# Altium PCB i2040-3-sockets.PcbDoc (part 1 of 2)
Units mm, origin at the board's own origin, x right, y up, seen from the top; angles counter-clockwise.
Board outline 210 x 90 mm, 2 copper layers (Top Layer, Bottom Layer), stack 1.575 mm thick; 146 components, 88 nets, 453 pads, 125 vias.
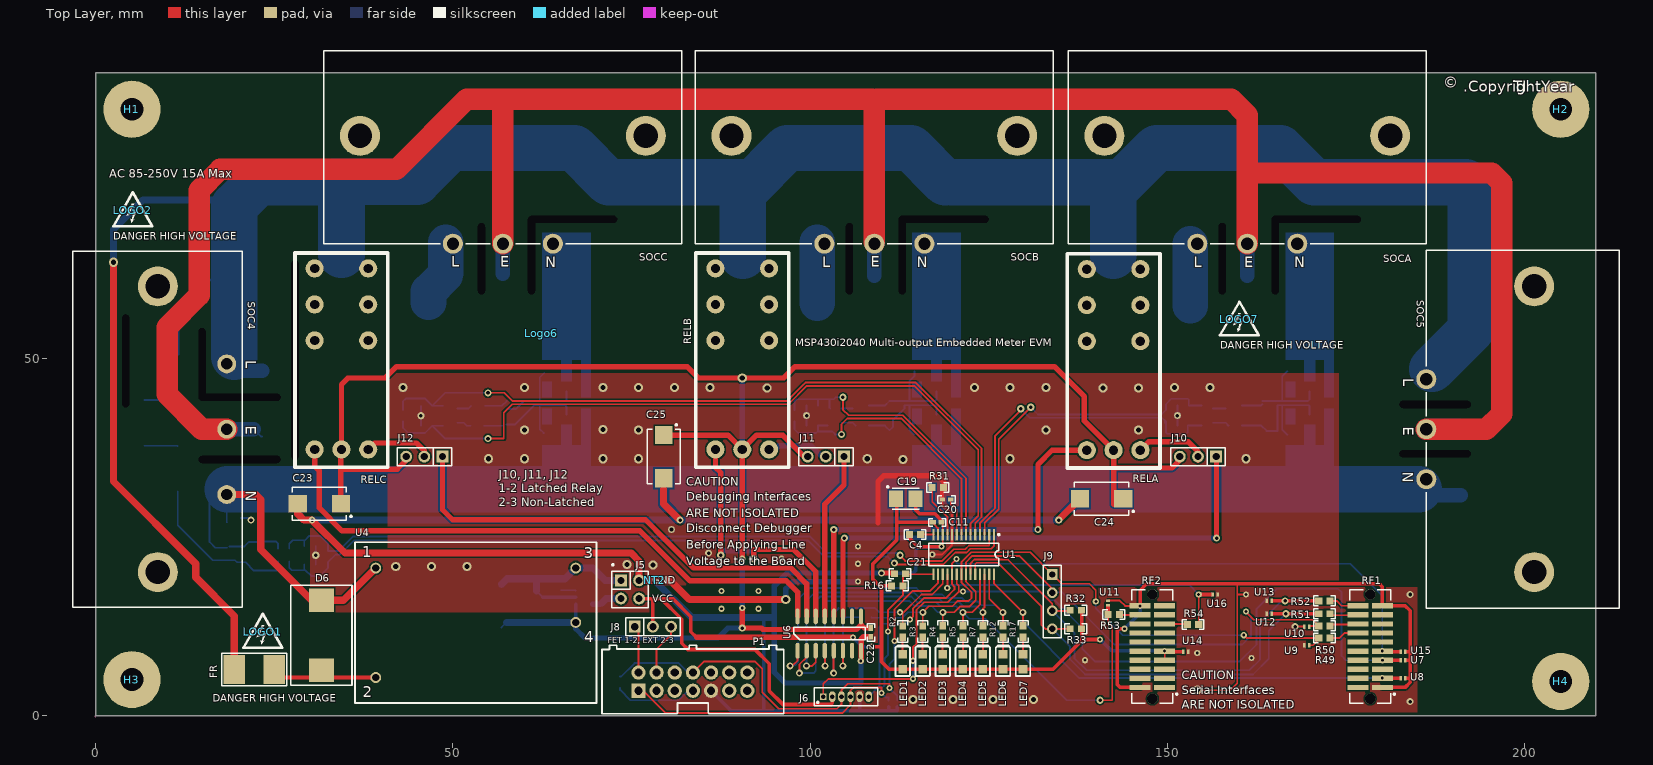
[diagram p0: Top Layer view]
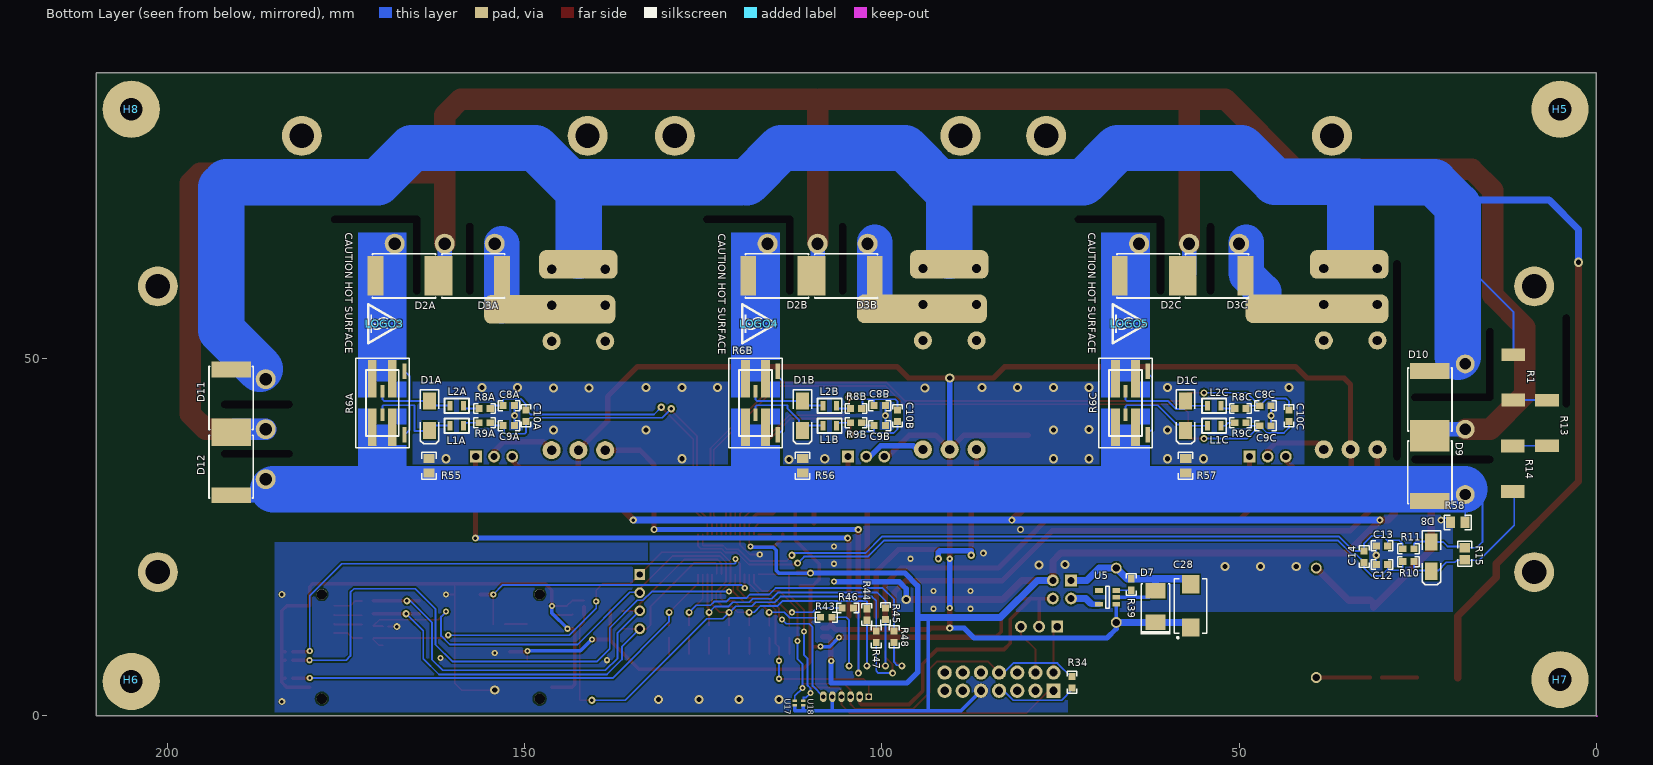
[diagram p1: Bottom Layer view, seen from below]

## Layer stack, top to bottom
Top Layer: signal copper 0.0356
Dielectric: core 1.5037, FR-4, Dk 4.8
Bottom Layer: signal copper 0.0356

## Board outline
0,0 0,90 210,90 210,0

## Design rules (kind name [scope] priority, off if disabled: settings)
AcuteAngle [All] p1: minimum=4.50000000000000E+0001 checktracksonly=FALSE
AssemblyTestPointUsage [All] p1: valid=2
Clearance Clearance_2 [InNet('DGND')] p1: gap=0.254
Clearance Clearance_1 [InNet('AGND')] p2: gap=0.254
Clearance Clearance_BoardEdge_MountingHoles [OnCopper and InComponentClass('Mounting Holes') vs IsKeepOut] p3: gap=1.016
Clearance Clearance_BoardEdge_Poly [OnCopper and InPoly vs IsKeepOut] p4: gap=0.635
Clearance Clearance_BoardEdge [OnCopper and Not InComponentClass('Logo') and not InComponentClass('FiducialMark') and not InRegion(1000,500,4000,800) and Not IsKeepout vs IsKeepOut] p5: gap=1.905
Clearance Clearance_Poly [InPolygon] p6: gap=0.635
Clearance [All] p7: gap=0.203
ComponentClearance ComponentClearance_Shunt [InComponentClass('Header') vs InComponentClass('Shunt')] p1: gap=0 collisioncheckmode=3 verticalgap=0 showdistances=TRUE
ComponentClearance ComponentClearance_Logo [InComponentClass('Logo')] p2: gap=0.5 collisioncheckmode=3 verticalgap=0.254 showdistances=TRUE
ComponentClearance ComponentClearance_ScrewToNut [(HasFootprint('NY PMS 440 0025 PH')) vs (HasFootprint('Keystone_1902C'))] p3: gap=0.127 collisioncheckmode=3 verticalgap=0.254 showdistances=TRUE
ComponentClearance ComponentClearance_MountingHoles [InComponentClass('Mounting Holes')] p4: gap=6.35 collisioncheckmode=3 verticalgap=2540 showdistances=TRUE
ComponentClearance ComponentClearance_SmallPassives [HasFootprint('0201*') or HasFootprint('0402*') or HasFootprint('0508') or HasFootprint('0603*') or HasFootprint('0612') or HasFootprint('0805*') or HasFootprint('0815*') or HasFootprint('0830*') or HasFootprint('1206*') or HasFootprint('1210*') or HasFootprint('1808*') or HasFootprint('1812*') or HasFootprint('1825*') or HasFootprint('2010*') or HasFootprint('2220*') or HasFootprint('2225*') or HasFootprint('2512*') or HasFootprint('2728*') or HasFootprint('3518*') vs HasFootprint('0201*') or HasFootprint('0402*') or HasFootprint('0508') or HasFootprint('0603*') or HasFootprint('0612') or HasFootprint('0805*') or HasFootprint('0815*') or HasFootprint('0830*') or HasFootprint('1206*') or HasFootprint('1210*') or HasFootprint('1808*') or HasFootprint('1812*') or HasFootprint('1825*') or HasFootprint('2010*') or HasFootprint('2220*') or HasFootprint('2225*') or HasFootprint('2512*') or HasFootprint('2728*') or HasFootprint('3518*')] p5: gap=0.508 collisioncheckmode=3 verticalgap=0.254 showdistances=TRUE
ComponentClearance ComponentClearance_THtoSMT [IsThruComponent vs IsSMTComponent] p6: gap=1 collisioncheckmode=3 verticalgap=0.762 showdistances=TRUE
ComponentClearance ComponentClearance_THtoTH [IsThruComponent vs IsThruComponent] p7: gap=1 collisioncheckmode=3 verticalgap=0.762 showdistances=TRUE
ComponentClearance [All] p8: gap=0.5 collisioncheckmode=3 verticalgap=0.254 showdistances=TRUE
DiffPairsRouting [All] p1: maxlimit=2.54 minlimit=0.254 mostfreqgap=0.254 maxuncoupledlength=25.4
FabricationTestPointUsage TestPointUsage [All] p1: valid=2 allowmultiple=FALSE
FabricationTestpoint Testpoint [All] p1: side=3 testpointundercomponent=TRUE minsize=1.016 maxsize=2.54 preferedsize=1.524 minholesize=0 maxholesize=1.016 preferedholesize=0.813 testpointgrid=0.025 allowsidetop=TRUE allowsidebottom=TRUE usegrid=TRUE gridtolerance=0
FanoutControl Fanout_LCC [IsLCC] p1: bgadir=Out bgaviamode=Centered fanoutstyle=Auto fanoutdirection=Alternating viagrid=0.025 // Fanout_LCC (Default Rule)
FanoutControl Fanout_BGA [IsBGA] p2: bgadir=Out bgaviamode=Centered fanoutstyle=Auto fanoutdirection=Alternating viagrid=0.025 // Fanout_BGA (Default Rule)
FanoutControl Fanout_Default [All] p4: bgadir=Out bgaviamode=Centered fanoutstyle=Auto fanoutdirection=Alternating viagrid=0.025 // Fanout_Default (Default Rule)
FanoutControl Fanout_Small [(CompPinCount < 5)] p5: bgadir=Out bgaviamode=Centered fanoutstyle=Auto fanoutdirection=OutThenIn viagrid=0.025 // Fanout_Small (Default Rule)
HoleSize [All] p1: absolutevalues=TRUE maxlimit=6.375 minlimit=0.203 maxpercent=80.000 minpercent=20.000
MinimumAnnularRing MinimumAnnularRing_ThermalPadVias [IsVia and InAnyComponent] p1: minimumring=0.15
MinimumAnnularRing [All] p2: minimumring=0.229
MinimumSolderMaskSliver MinimumSolderMaskSliver_Logo [InComponentClass('Logo') vs InComponentClass('Logo')] p1: minsoldermaskwidth=0.018
MinimumSolderMaskSliver [All] p2: minsoldermaskwidth=0.1
PlaneClearance [All] p1: clearance=0.254
PlaneConnect [All] p1: planeconnectstyle=Direct reliefexpansion=0.254 reliefentries=4 reliefconductorwidth=0.254 reliefairgap=0.254
PolygonConnect PolygonConnect_1 [InNet('DGND') vs IsNamedPolygon('Top Layer-DGND')] p1: connectstyle=Direct reliefconductorwidth=0.254 reliefentries=4 polygonreliefangle="90 Angle" airgapwidth=0.254
PolygonConnect [InNet('AGND')] p2: connectstyle=Direct reliefconductorwidth=0.254 reliefentries=4 polygonreliefangle="90 Angle" airgapwidth=0.254
RoomDefinition Protection [InComponentClass('Protection')] p1: confinementstyle=ConfineOut formatcopy=TRUE lockcomponents=FALSE outline 150,140 150,170 80,170 80,140.4 80.4,140
RoomDefinition i2040-3-sockets [InComponentClass('i2040-3-sockets')] p2: confinementstyle=ConfineOut formatcopy=TRUE lockcomponents=FALSE outline 176,133 236,133 236,162 176.2,162 176,162.2
RoomDefinition Hardware [InComponentClass('Hardware')] p3: confinementstyle=ConfineOut formatcopy=TRUE lockcomponents=FALSE outline 233.426,70.104 244.094,70.104 244.094,116.078 233.426,116.078
RoutingVias ThermalPadVias [IsVia and InAnyComponent] p1: holewidth=0.2 width=0.5 viastyle="Through Hole" minholewidth=0.2 minwidth=0.5 maxholewidth=0.33 maxwidth=0.6
RoutingVias [All] p2: holewidth=0.406 width=0.864 viastyle="Through Hole" minholewidth=0.2 minwidth=0.66 maxholewidth=1.016 maxwidth=1.651
SMDToCorner [All] p1: distance=30000
SilkToSilkClearance [All] p1: silktosilkclearance=0.127
SilkscreenOverComponentPads [All] p1: minsilkscreentomaskgap=0.127
SolderMaskExpansion [All] p1: expansion=0.05
Width [All] p1: maxlimit=7 minlimit=0.152 preferedwidth=0.254 checkconnectedcopper=TRUE
13 further rules are at their usual default settings.

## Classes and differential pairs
component class "Mounting Holes": H1 H2 H3 H4
component class Logo: Logo6
component class Hardware: H1 H2 H3 H4 H5 H6 H7 H8 LOGO1 LOGO2 LOGO3 LOGO4 LOGO5 Logo6 LOGO7 Logo?
component class Header: J5 J8 J10 J11 J12
component class i2040-3-sockets: 0.8 C4 C8A C8B C8C C9A C9B C9C C10A C10B C10C C11 C12 C13 C14 C19 C20 C21 C22 C23 C24 C25 C28 D1A D1B D1C D6 D7 D8 FR J5 J6 J8 J9 J10 J11 J12 L1A L1B L1C L2A L2B L2C LED1 LED2 LED3 LED4 LED5 LED6 LED7 NT2 P1 R1 R2 R3 R4 R5 R6A R6B R6C R7 R8A R8B R8C R9A R9B R9C R10 R11 R12 R13 R14 R15 R16 R17 R31 R32 R33 R34 R39 R43 R44 R45 R46 R47 R48 R49 R50 R51 R52 R53 R54 R55 R56 R57 R58 RELA RELB RELC RF1 RF2 SOC4 SOC5 SOCA SOCB SOCC U1 U4 U5 U6
component class Protection: D2A D2B D2C D3A D3B D3C D9 D10 D11 D12 U7 U8 U9 U10 U11 U12 U13 U14 U15 U16 U17 U18

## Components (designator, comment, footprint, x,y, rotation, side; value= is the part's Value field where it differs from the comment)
C4 "470nF" 0603 114.7,25.4 r180 top
C8A "06035A470JAT2A" 0603 152.218,43.434 r0 bottom
C8B "06035A470JAT2A" 0603 100.318,43.434 r0 bottom
C8C "06035A470JAT2A" 0603 46.318,43.425 r0 bottom
C9A "06035A470JAT2A" 0603 152.218,40.634 r180 bottom
C9B "06035A470JAT2A" 0603 100.318,40.634 r180 bottom
C9C "06035A470JAT2A" 0603 46.318,40.625 r180 bottom
C10A "GRM188R71C153KA01D" 0603 149.818,42.034 r90 bottom
C10B "GRM188R71C153KA01D" 0603 97.818,42.034 r90 bottom
C10C "GRM188R71C153KA01D" 0603 43.018,42.025 r90 bottom
C11 "0.1uF" 0402 117.8,27.1 r0 top
C12 "06035A470JAT2A" 0603 30,21.2 r0 bottom
C13 "06035A470JAT2A" 0603 30,23.8 r180 bottom
C14 "GRM188R71C153KA01D" 0603 32.5,22.3 r90 bottom
C19 "293D106X0010B2TE3" 3528-21 113.4,30.4 r0 top
C20 "0.1uF" 0402 119.1,30.3 r180 top
C21 "C0603X222K5RACTU" 0603 112.6,19.9 r180 top
C22 "0.1uF" 0402 108.5,11.7 r270 top
C23 "293D227X96R3D2TE3" 7343-31 31.3,29.7 r180 top
C24 "293D227X96R3D2TE3" 7343-31 140.8,30.4 r180 top
C25 "293D227X96R3D2TE3" 7343-31 79.5,36.3 r270 top
C28 "293D227X96R3D2TE3" 7343-31 56.8,15.4 r90 bottom
D1A "SMAJ5.0CA" DSO-C2/X1.8 163.318,42.025 r270 bottom
D1B "SMAJ5.0CA" DSO-C2/X1.8 111.118,42.025 r270 bottom
D1C "SMAJ5.0CA" DSO-C2/X1.8 57.518,42.025 r270 bottom
D2A "V430CH8T" V430CH8T 166.9,61.6 r0 bottom
D2B "V430CH8T" V430CH8T 114.7,61.6 r0 bottom
D2C "V430CH8T" V430CH8T 62.7,61.6 r0 bottom
D3A "V430CH8T" V430CH8T 157.2,61.6 r180 bottom
D3B "V430CH8T" V430CH8T 105,61.6 r180 bottom
D3C "V430CH8T" V430CH8T 53.1,61.6 r180 bottom
D6 "V320SM7" V320SM7 31.6,11.3 r90 top
D7 "SMBJ7.0A-13-F" SMB 61.7,15.3 r90 bottom
D8 "SMAJ5.0CA" DSO-C2/X1.8 23.1,22.3 r270 bottom
D9 "V430CH8T" V430CH8T 23.3,34.1 r270 bottom
D10 "V430CH8T" V430CH8T 23.3,44.3 r90 bottom
D11 "V430CH8T" V430CH8T 191.1,44.5 r90 bottom
D12 "V430CH8T" V430CH8T 191.1,34.9 r90 bottom
FR "6125FA1A" 6125FA 22.2,6.5 r180 top
H1 "NY PMS 440 0025 PH" "NY PMS 440 0025 PH"#1 5.08,84.92 r0 top locked
H2 "NY PMS 440 0025 PH" "NY PMS 440 0025 PH"#1 205.072,84.92 r0 top locked
H3 "NY PMS 440 0025 PH" "NY PMS 440 0025 PH"#1 5.08,5.08 r0 top locked
H4 "NY PMS 440 0025 PH" "NY PMS 440 0025 PH"#2 205.072,5.08 r0 top locked
H5 "1902C" Keystone_1902C#1 5.08,84.92 r180 bottom locked
H6 "1902C" Keystone_1902C#2 205.075,5.08 r180 bottom
H7 "1902C" Keystone_1902C#1 5.08,5.08 r180 bottom locked
H8 "1902C" Keystone_1902C#1 205.072,84.92 r180 bottom locked
J5 "TSW-102-07-G-D" TSW-102-07-G-D 74.8,17.7 r270 top
J6 "Used in BOM report" "6-pin header (1.27mm)" 105,2.7 r0 top
J8 "PBC03SAAN" PBC03SAAN 78,12.5 r0 top
J9 "Header 4" HDR1X4 133.9,19.8 r270 top
J10 "PBC03SAAN" PBC03SAAN 154.3,36.3 r180 top
J11 "PBC03SAAN" PBC03SAAN 102.2,36.3 r180 top
J12 "PBC03SAAN" PBC03SAAN 46,36.3 r180 top
L1A "BLM21BD121SN1D" YW0805 159.518,40.634 r0 bottom
L1B "BLM21BD121SN1D" YW0805 107.318,40.634 r0 bottom
L1C "BLM21BD121SN1D" YW0805 53.5,40.6 r0 bottom
L2A "BLM21BD121SN1D" YW0805 159.518,43.434 r0 bottom
L2B "BLM21BD121SN1D" YW0805 107.318,43.434 r0 bottom
L2C "BLM21BD121SN1D" YW0805 53.5,43.4 r0 bottom
LED1 "Used in BOM report" 0805-LED 112.952,7.606 r90 top
LED2 "Used in BOM report" 0805-LED 115.752,7.606 r90 top
LED3 "Used in BOM report" 0805-LED 118.552,7.617 r90 top
LED4 "Used in BOM report" 0805-LED 121.382,7.617 r90 top
LED5 "Used in BOM report" 0805-LED 124.182,7.617 r90 top
LED6 "Used in BOM report" 0805-LED 127,7.617 r90 top
LED7 "Used in BOM report" 0805-LED 129.8,7.617 r90 top
LOGO1 "DANGER HIGH VOLTAGE" IEC_HighVoltage_Small 23.4,11.8 r0 top
LOGO2 "DANGER HIGH VOLTAGE" IEC_HighVoltage_Small 5.2,70.8 r0 top
LOGO3 "CAUTION HOT SURFACE" IEC_HotSurface_Small 169.562,54.9 r270 bottom
LOGO4 "CAUTION HOT SURFACE" IEC_HotSurface_Small 117.186,54.9 r270 bottom
LOGO5 "CAUTION HOT SURFACE" IEC_HotSurface_Small 65.3,54.9 r270 bottom
Logo6 "Texas Instruments" TI_Stacked_SolderMask_Medium 62.4,53.6 r0 top
LOGO7 "DANGER HIGH VOLTAGE" IEC_HighVoltage_Small 160.1,55.5 r0 top
NT2 "Net-Tie" Net-Tie_10mil 78.23,18.97 r180 top net-tie
P1 "MHDR2X7" 2X7BOXHEADER 83.6,4.8 r0 top
R1 "330k" R2512 11.6,47.4 r270 bottom
R2 "390" 0603 112.97,11.806 r270 top
R3 "390" 0603 115.77,11.806 r270 top
R4 "390" 0603 118.57,11.817 r270 top
R5 "390" 0603 121.4,11.817 r270 top
R6A "Used in BOM report" "CURRENT SENSING PAD" 169.924,43.8 r90 bottom
R6B "Used in BOM report" "CURRENT SENSING PAD" 117.7,43.8 r90 bottom
R6C "Used in BOM report" "CURRENT SENSING PAD" 65.9,43.8 r90 bottom
R7 "390" 0603 124.2,11.817 r270 top
R8A "1.00k" 0603 155.618,43.034 r180 bottom
R8B "1.00k" 0603 103.618,43.034 r180 bottom
R8C "1.00k" 0603 49.818,43.025 r180 bottom
R9A "1.00k" 0603 155.618,41.034 r180 bottom
R9B "1.00k" 0603 103.618,41.034 r180 bottom
R9C "1.00k" 0603 49.818,41.025 r180 bottom
R10 "100" 0603 26.3,21.6 r0 bottom
R11 "1.00k" 0603 26.3,23.4 r0 bottom
R12 "390" 0603 127.018,11.817 r270 top
R13 "330k" R2512 6.9,41 r270 bottom
R14 "330k" R2512 11.7,34.6 r270 bottom
R15 "1.50k" 0805 18.4,22.7 r270 bottom
R16 "4.7k" 0603 112.2,18.2 r0 top
R17 "390" 0603 129.818,11.817 r270 top
R31 "Open" 0603 117.873,31.973 r180 top
R32 "Open" 0603 137.2,14.8 r0 top
R33 "Open" 0603 137.2,12.2 r0 top
R34 "330" 0603 73.4,4.7 r270 bottom
R39 "0" 0603 65.1,18.4 r90 bottom
R43 "0" 0603 107.8,13.8 r180 bottom
R44 "0" 0603 102.1,14.2 r270 bottom
R45 "0" 0603 99.5,14.3 r270 bottom
R46 "0" 0603 104.8,15.1 r180 bottom
R47 "0" 0603 100.8,11.1 r270 bottom
R48 "0" 0603 98.3,11.1 r270 bottom
R49 "0" 0603 172,10.9 r180 top
R50 "0" 0603 172,12.6 r180 top
R51 "0" 0603 172,14.3 r180 top
R52 "0" 0603 172,16.1 r180 top
R53 "0" 0603 142.5,14.2 r180 top
R54 "0" 0603 153.6,12.8 r180 top
R55 "CRCW08050000Z0EA" 0805_HV 163.4,35 r270 bottom
R56 "CRCW08050000Z0EA" 0805_HV 111.1,35 r270 bottom
R57 "CRCW08050000Z0EA" 0805_HV 57.5,35 r270 bottom
R58 "CRCW08050000Z0EA" 0805_HV 19.4,27.1 r180 bottom
RELA "RT314F05" "TE RELAY TYPE A" 142.486,64.7 r90 top
RELB "RT314F05" "TE RELAY TYPE A" 90.508,64.8 r90 top
RELC "RZ031A4D005" "TE RELAY TYPE A" 34.4,64.8 r90 top
RF1 "TFM-110-02-S-D-A-K-TR" Samtec_TFM-110-02-S-D-A-K 178.4,9.7 r90 top
RF2 "TFM-110-02-S-D-A-K-TR" Samtec_TFM-110-02-S-D-A-K 147.92,9.7 r90 top
SOC4 "Plug AC Male" IEC9.14-2H3 0,40.132 r180 top locked
SOC5 "Plug AC Female" IEC7-2H3 210.058,40.132 r0 top locked
SOCA "Plug AC Female" IEC7-2H3 161.2,89.9 r90 top locked
SOCB "Plug AC Female" IEC7-2H3 109,89.9 r90 top locked
SOCC "Plug AC Female" IEC7-2H3 57,89.9 r90 top locked
U1 "MSP430i2040PW" TSSO10x6-G28 121.5,22.6 r180 top
U4 "Used in BOM report" VSK-S1 39.2,20.7 r0 top
U5 "TPS77033DBVT" DBV0005A_N 68.4,16.6 r0 bottom
U6 "ULN2003LVDR" D0016A_N 102.698,11.529 r90 top
U7 "TPD1E10B06DPYT" DPY0002A_N 183,7.8 r0 top
U8 "TPD1E10B06DPYT" DPY0002A_N 183,5.3 r0 top
U9 "TPD1E10B06DPYT" DPY0002A_N 169.5,9.9 r180 top
U10 "TPD1E10B06DPYT" DPY0002A_N 169.5,12.5 r180 top
U11 "TPD1E10B06DPYT" DPY0002A_N 141.7,15.8 r90 top
U12 "TPD1E10B06DPYT" DPY0002A_N 164.3,14.3 r180 top
U13 "TPD1E10B06DPYT" DPY0002A_N 164.3,16.1 r180 top
U14 "TPD1E10B06DPYT" DPY0002A_N 152.6,9 r0 top
U15 "TPD1E10B06DPYT" DPY0002A_N 183,9 r0 top
U16 "TPD1E10B06DPYT" DPY0002A_N 156.7,17 r0 top
U17 "TPD1E10B06DPYT" DPY0002A_N 112.2,1.8 r270 bottom
U18 "TPD1E10B06DPYT" DPY0002A_N 111,1.8 r270 bottom

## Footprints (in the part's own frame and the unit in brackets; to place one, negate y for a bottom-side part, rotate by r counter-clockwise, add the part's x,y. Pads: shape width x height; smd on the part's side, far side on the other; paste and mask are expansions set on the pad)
2X7BOXHEADER [mm]
  rect 2x2 hole 1.15: 1(-7.62,-1.27)
  round 2 hole 1.15: 2(-7.62,1.27) 3(-5.08,-1.27) 4(-5.08,1.27) 5(-2.54,-1.27) 6(-2.54,1.27) 7(0,-1.27) 8(0,1.27) 9(2.54,-1.27) 10(2.54,1.27) 11(5.08,-1.27) 12(5.08,1.27) 13(7.62,-1.27) 14(7.62,1.27)
  silkscreen extent -12.72,-4.5 12.72,5.08
"6-pin header (1.27mm)" [mm] "6 pin header 1.27mm"
  rect 0.9x0.9 hole 0.65 mask+0: 1(-3.15,0)
  oval 0.9x1.5 hole 0.65 mask+0: 2(-1.88,0) 3(-0.61,0) 4(0.66,0) 5(1.93,0) 6(3.2,0)
  silkscreen extent -4.42,-1.27 4.47,1.27
0402 [mm] "0402 from SM-752 data"
  rect 0.8x0.6 smd: 1(-0.6,0) 2(0.6,0)
  silkscreen extent -1.22,-0.52 1.22,0.52, body extent -0.55,-0.3 0.55,0.3, height 0.6
0603 [mm] "0603 from SM-752 data"
  rect 1x0.95 smd: 1(-0.8,0) 2(0.8,0)
  silkscreen extent -1.52,-0.69 1.52,0.69, body extent -0.87,-0.47 0.87,0.47, height 0.85
0805 [mm] "0805 from SM-752 data"
  rect 1.3x1.5 smd: 1(-0.85,0) 2(0.85,0)
  silkscreen extent -1.72,-0.97 1.72,0.97, body extent -1.1,-0.72 1.1,0.72, height 1.1
0805-LED [mm]
  rect 1.2x1.2 smd: 1(-1.055,-0.005) 2(1.045,-0.005)
  silkscreen extent -2.01,-1.02 2.26,1.01
0805_HV [mil] "0805 with 30mil clearance between pads"
  rect 50x63 smd: 1(-40,0) 2(40,0)
  silkscreen extent -74,-40 74,40, body extent -43,-29 43,29, height 43
3528-21 [mm] "Medium Density IPC, based on SM-782 section 8.4"
  rect 1.95x2.25 smd: 1(-1.375,0) 2(1.375,0)
  silkscreen extent -2.66,-1.5 1.9,1.79, body extent -1.85,-1.5 1.85,1.5, height 2.1
6125FA [mm] "Cooper Bussman 6125FA Brick Fuses, recommended land pattern OC-2531 Rev. I 3/07"
  rect 3x4 smd: 1(-2.8,0) 2(2.8,0)
  silkscreen extent -4.58,-2.27 4.57,2.28, body extent -3.17,-1.42 3.17,1.41, height 2.84
7343-31 [mm] "Medium Density based on Kemet T495 dimensions"
  rect 2.55x2.45 smd: 1(-3.025,0) 2(3.025,0)
  silkscreen extent -4.56,-2.3 3.8,2.3, body extent -3.8,-2.3 3.8,2.3, height 3.1
"CURRENT SENSING PAD" [mm] "Current Sensing Pad for 2512"
  rect 5.2x1.2 smd: 1(3.4,-1.4) 1(3.4,1.4) 2(-3.4,-1.4) 2(-3.4,1.4)
  rect 1.7x0.6 smd: 3(1.65,0) 4(-1.65,0)
  rect 2.2x0.6 smd: 5(4.45,-3.1) 6(-4.45,-3.1)
  Top Layer region: 0.8,-2 3,-2 3,-3.4 0.8,-3.4
  Top Layer region: -3,-2 -0.8,-2 -0.8,-3.4 -3,-3.4
  Top Layer region: 3,0.8 6,0.8 6,-0.8 3,-0.8
  Top Layer region: -6,0.8 -3,0.8 -3,-0.8 -6,-0.8
  Top Layer region: -6,3.4 -0.8,3.4 -0.8,2 -6,2
  Top Layer region: 0.8,3.4 6,3.4 6,2 0.8,2
  silkscreen extent -6.25,-3.75 6.25,3.75
D0016A_N [mm] "SOIC, 16-Leads, Body 9.9x3.9mm, Pitch 1.27mm, IPC Medium Density"
  oval 2.2x0.6 smd: 1(-2.4,4.445) 2(-2.4,3.175) 3(-2.4,1.905) 4(-2.4,0.635) 5(-2.4,-0.635) 6(-2.4,-1.905) 7(-2.4,-3.175) 8(-2.4,-4.445) 9(2.4,-4.445) 10(2.4,-3.175) 11(2.4,-1.905) 12(2.4,-0.635) 13(2.4,0.635) 14(2.4,1.905) 15(2.4,3.175) 16(2.4,4.445)
  silkscreen extent -0.9,-5 0.9,5, body extent -3,-4.95 3,4.95, height 1.59
DBV0005A_N [mm] "SOT23, 5-Leads, Body 2.9x1.6mm, Pitch 0.95mm, Lead Span 2.8mm, IPC Medium Density"
  rect 1.1x0.65 smd: 1(-1.2,0.95) 2(-1.2,0) 3(-1.2,-0.95) 4(1.2,-0.95) 5(1.2,0.95)
  silkscreen extent -0.25,-1.55 0.25,1.55, body extent -1.42,-1.46 1.42,1.46, height 1.08
DPY0002A_N [mm] "DFN, 2-Leads, Body 1.0x0.6x0.4mm, IPC Medium Density"
  rect 0.35x0.62 smd: 1(-0.34,0) 2(0.34,0)
  body extent -0.5,-0.3 0.5,0.3, height 0.4
DSO-C2/X1.8 [mm] "DO-214-AC/SMA; 2 C-Bend Leads; Body 5 x 2.7 mm, inc. leads (LxW)"
  rect 2.4x1.8 smd: 1(-2.05,0) 2(2.05,0)
  silkscreen extent -3.65,-1.3 3.95,1.3
HDR1X4 [mm] "Connector; Header; 4 Position"
  rect 1.5x1.5 hole 0.9: 1(0,0)
  round 1.5 hole 0.9: 2(2.54,0) 3(5.08,0) 4(7.62,0)
  silkscreen extent -1.27,-1.27 8.89,1.27
IEC7-2H3 [mm] "Mains Power Outlet, IEC60 320-2-2 F, PC Flange Rear Mount"
  round 2.8 hole 1.7: 1(-23.8,7) 2(-23.8,-7) 3(-23.8,0)
  round 5.6 hole 3.4: MH1(-8.7,20) MH2(-8.7,-20)
  silkscreen extent -23.8,-25.05 3.2,25.05
IEC9.14-2H3 [mm] "Mains Power Inlet, IEC60 320-1 C14, PC Flange Rear Mount"
  round 2.65 hole 1.6: 1(-18.35,-9.14) 2(-18.35,9.14) 3(-18.35,0)
  round 5.6 hole 3.4: MH1(-8.7,20) MH2(-8.7,-20)
  silkscreen extent -20.5,-24.9 3.2,24.9
IEC_HighVoltage_Small [mm]
  silkscreen extent -2.72,-2.24 2.72,2.47
IEC_HotSurface_Small [mm]
  silkscreen extent -2.72,-2.36 2.72,2.35
Keystone_1902C#1 [mm] "Hex Standoff, 4-40 threaded, nylon"
  body extent -3.68,-3.2 3.71,3.2, height 12.73
Keystone_1902C#2 [mm] "Hex Standoff, 4-40 threaded, nylon"
  round 0.025 on Mech4: 0(0,0)
  body extent -3.68,-3.2 3.71,3.2, height 12.73
Net-Tie_10mil [mil] "10mil net tie, no solder mask opening, no solder paste"
  rect 10x10 smd paste-5 mask-5: 1(-10,0) 2(10,0)
  Top Layer region: -6,5 6,5 6,-5 -6,-5
"NY PMS 440 0025 PH"#1 [mm] "4-40 nylon screw and mounting hole"
  round 8 hole 3.2: 1(0,0)
  body extent -3.3,-3.3 3.3,3.3, height 2.69
"NY PMS 440 0025 PH"#2 [mm] "4-40 nylon screw and mounting hole"
  round 8 hole 3.2: 1(0,-0.254)
  body extent -3.3,-3.3 3.3,3.3, height 2.69
PBC03SAAN [mm] "Sullins 100mil, 1x3, 230 mil above insulator"
  rect 1.65x1.65 hole 1.016: 1(-2.54,0)
  round 1.65 hole 1.016: 2(0,0) 3(2.54,0)
  silkscreen extent -3.81,-1.27 3.81,1.27, body extent -3.81,-1.27 3.81,1.27, height 8.38
R2512 [mil]
  rect 70x130 smd: 1(-125,0) 2(125,0)
Samtec_TFM-110-02-S-D-A-K [mm] "Samtec"
  rect 0.74x2.92 smd paste+0: 1(-5.715,-1.715) 2(-5.715,1.715) 3(-4.445,-1.715) 4(-4.445,1.715) 5(-3.175,-1.715) 6(-3.175,1.715) 7(-1.905,-1.715) 8(-1.905,1.715) 9(-0.635,-1.715) 10(-0.635,1.715) 11(0.635,-1.715) 12(0.635,1.715) 13(1.905,-1.715) 14(1.905,1.715) 15(3.175,-1.715) 16(3.175,1.715) 17(4.445,-1.715) 18(4.445,1.715) 19(5.715,-1.715) 20(5.715,1.715)
  round 1.45 hole 1.45 unplated paste+0: ""(-7.305,0) ""(7.305,0)
  silkscreen extent -7.94,-3.51 7.94,2.86, body extent -7.95,-2.98 7.93,2.99, height 5.85
SMB [mm] "Molded Diode, 2-Leads, Body 5.4x3.6mm, IPC Medium Density, based on OnSemi component dimensions"
  rect 2.159x2.743 smd: 1(-2.21,0) 2(2.21,0)
  silkscreen extent -3.94,-2.08 3.17,2.08, body extent -2.7,-1.8 2.7,1.8, height 2.32
"TE RELAY TYPE A" [mm] "TE Relay type A footprint"
  round 2.54 hole 1.3: 1(-27.5,3.75) 2(-27.5,-3.75) 3(-12.24,3.75) 4(-12.24,-3.75) 5(-7.2,3.75) 6(-7.2,-3.75) 7(-2.16,3.75) 8(-2.16,-3.75) 9(-27.5,0)
  silkscreen extent -30,-6.5 0,6.5, body extent -30.25,-6.75 0.25,6.75, height 15.7
TI_Stacked_SolderMask_Medium [mm]
  rect 0x0 smd paste-4.978 mask-4.978: 0(0,0)
TSSO10x6-G28 [mm] "Shrink Small Outline; 28 Leads; Body Width 4.4 mm; Pitch 0.65 mm"
  rect 0.3x1.65 smd: 1(-4.225,-2.775) 2(-3.575,-2.775) 3(-2.925,-2.775) 4(-2.275,-2.775) 5(-1.625,-2.775) 6(-0.975,-2.775) 7(-0.325,-2.775) 8(0.325,-2.775) 9(0.975,-2.775) 10(1.625,-2.775) 11(2.275,-2.775) 12(2.925,-2.775) 13(3.575,-2.775) 14(4.225,-2.775) 15(4.225,2.775) 16(3.575,2.775) 17(2.925,2.775) 18(2.275,2.775) 19(1.625,2.775) 20(0.975,2.775) 21(0.325,2.775) 22(-0.325,2.775) 23(-0.975,2.775) 24(-1.625,2.775) 25(-2.275,2.775) 26(-2.925,2.775) 27(-3.575,2.775) 28(-4.225,2.775)
  silkscreen extent -5.05,-2.9 4.9,1.55
TSW-102-07-G-D [mm] "Samtec 100mil, 2x2, 230 mil above insulator"
  rect 1.65x1.65 hole 1.016 mask+0: 1(-1.27,-1.27)
  round 1.65 hole 1.016 mask+0: 2(-1.27,1.27) 3(1.27,-1.27) 4(1.27,1.27)
  silkscreen extent -3.56,-2.54 2.54,2.54, body extent -2.54,-2.54 2.54,2.54, height 8.38
V320SM7 [mm] "SMD MOV"
  rect 3.3x3.5 smd: 1(-4.9,0) 2(4.9,0)
  silkscreen extent -7,-4.3 7,4.3, body extent -6,-4.1 6,4, height 6
V430CH8T [mm] "MOV"
  rect 2.21x5.5 smd: 1(-4,0) 2(4,0)
  silkscreen extent -4.4,-3.1 4.4,3.1, body extent -4.1,-2.5 4.1,2.5, height 2.03
VSK-S1 [mil] "On board block power supply"
  round 60 hole 39.37: 1(0,0) 2(0,-603.31) 3(1102.36,0) 4(1102.36,-300)
  silkscreen extent -114,-744 1217,142, body extent -98,-720 1193,118, height 709
YW0805 [mm]
  rect 0.7x1.3 smd: 1(0.946,0) 2(-0.954,0)
  silkscreen extent -1.71,-1.02 1.7,1.02

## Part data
C4: library part Capacitor, "CAP, CERM, 470nF, 16V, [TempCo], xx%, [PackageReference]"
C8A C8B C8C C9A C9B C9C C12 C13: "CAP, CERM, 47pF, 50V, +/-5%, C0G/NP0, 0603"
C10A C10B C10C C14: "CAP, CERM, 0.015uF, 16V, +/-10%, X7R, 0603"
C11 C20 C22: library part C1005X5R1A104K, "CAP, CERM, 0.1uF, 10V, +/-10%, X5R, 0402"
C19: "CAP, TANT, 10uF, 10V, +/-20%, 2.5 ohm, 3528-21 SMD"
C21: "CAP, CERM, 2200pF, 50V, +/-10%, X7R, 0603"
C23 C24 C25 C28: "CAP, TANT, 220uF, 6.3V, +/-10%, 0.6 ohm, 7343-31 SMD"
D2A D2B D2C D3A D3B D3C D9 D10 D11 D12: "VARISTOR 389V 250A 2-SMD"
D7: "Diode, TVS, Uni, 7V, 600W, SMB"
FR: "Fuse, 1A,125V, SMD"
H1 H2 H3 H4: "Machine Screw, Round, #4-40 x 1/4, Nylon, Philips panhead"
H5 H6 H7 H8: "Standoff, Hex, 0.5\"L #4-40 Nylon"
J5: "Header, TH, 100mil, 2x2, Gold plated, 230 mil above insulator"
J6: library part "6 pin header (1.27mm)"
J8 J10 J11 J12: "Header, TH, 100mil, 1x3, Gold plated, 230 mil above insulator"
J9: "Header, 4-Pin"
L1A L1B L1C L2A L2B L2C: library part Inductor, "Inductor, FERRITE CHIP 120 OHM 0805"
LED1 LED5: library part LED-0805, "Red"
LED2 LED6: library part LED-0805, "Green"
LED3 LED7: library part LED-0805, "Blue"
LED4: library part LED-0805, "White"
LOGO1 LOGO2 LOGO7: library part IEC_HighVoltage, "IEC 61010-1 High Voltage Warning"
LOGO3 LOGO4 LOGO5: library part IEC_HotSurface, "IEC 61010-1 Hot Surface Warning"
Logo6: library part TI_Logo, "Texas Instrument Corporate Signature"
NT2: "Single point connection between nets."
P1: "Header, 7-Pin, Dual row"
R1 R13 R14: library part R2512, "Resistor, 330kOhm, 1W, 1%"
R2 R3 R4 R5 R7 R12 R17: library part RC0603JR-07390RL, "RES, 390 ohm, 5%, 0.1W, 0603"
R6A R6B R6C: library part ULRB12512R0005FLFSLT, "Shunt Resistor"
R8A R8B R8C R9A R9B R9C R11: library part CRCW06031K00FKEA, "RES, 1.00k ohm, 1%, 0.1W, 0603"
R10: library part CRCW0603100RFKEA, "RES, 100 ohm, 1%, 0.1W, 0603"
R15: library part CRCW08051K50FKEA, "RES, 1.50k ohm, 1%, 0.125W, 0805"
R16: library part CRCW06034K70JNEA, "RES, 4.7k ohm, 5%, 0.1W, 0603"
R31: library part Resistor, "RES, Open ohm, x%, xW, 0603"
R32 R33: library part Resistor, "RES, xxx ohm, x%, xW, [PackageReference]"
R34: library part CRCW0603330RJNEA, "RES, 330 ohm, 5%, 0.1W, 0603"
R39 R43 R44 R45 R46 R47 R48 R49 R50 R51 R52 R53 R54: library part CRCW06030000Z0EA, "RES, 0 ohm, 5%, 0.1W, 0603"
R55 R56 R57 R58: "RES, 0 ohm, 5%, 0.125W, 0805"
RELA RELB: "General Purpose Relays 5V 16A 1CO THT POWER RELAY"
RELC: library part RZ03-1A4-D005, "RELAY GEN PURPOSE SPST 16A 5V"
RF1 RF2: "CONN SHRD HDR HDR 20 POS 1.27MM SLDR ST SMD"
SOC4: "IEC Mains Power Inlet, EN60 320-1 C14 Class I Cold Condition, PC Flange Rear Mount, Chassis Plug"
SOC5 SOCA SOCB SOCC: "IEC Mains Power Outlet, EN60 320-2-2 F Class I, PC Flange Rear Mount, Chassis Socket"
U1: library part MSP430i2040, "MSP430i2040"
U4: library part VSK-S2-5U, "POWER SUPPLY SWITCHING 5V 2W"
U5: library part TPS76133DBVR, "LOW-POWER 50-mA 3.3 V LDO LINEAR REGULATORS, DBV0005A"
U6: library part ULN2003LVD, "7-Channel Relay and Inductive Load Sink Driver, D0016A"
U7 U8 U9 U10 U11 U12 U13 U14 U15 U16 U17 U18: "ESD Protection in 0402 Package with 10 pF Capacitance and 6 V Breakdown, 1 Channel, -40 to +125 degC, 2-pin X2SON (DPY)"

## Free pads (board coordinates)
  round 0 hole 1 slot 13 at 90 deg: 0(4.2,49.7)
  round 0 hole 1 slot 10 at 90 deg: 0(14.9,49.3) 0(54,64) 0(105.5,64) 0(157.7,64)
  round 0 hole 1 slot 11.5 at 0 deg: 0(20.15,35.9) 0(20.15,44.6)
  round 0 hole 1 slot 28 at 90 deg: 0(27.901,49.8)
  rrect50% 11x4 smd far side paste+0 mask+0: 0(34.6,63.2) 0(90.6,63.2) 0(142.5,63.2)
  rrect50% 20x4 smd far side paste+0 mask+0: 0(39.1,57)
  round 0 hole 1 slot 11 at 90 deg: 0(61,64.5) 0(112.9,64.5) 0(165.1,64.5)
  round 0 hole 1 slot 12.5 at 0 deg: 0(66.75,69.5) 0(118.75,69.5) 0(170.85,69.5)
  rrect50% 18.2x4 smd far side paste+0 mask+0: 0(94.4,57)
  rrect50% 18.4x4 smd far side paste+0 mask+0: 0(146.5,56.9)
  round 0 hole 1 slot 10 at 0 deg: 0(187.5,36.7) 0(187.5,43.6)

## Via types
v1: diameter 1, hole 0.5, Top Layer to Bottom Layer, 44 vias
v2: diameter 0.864, hole 0.406, Top Layer to Bottom Layer, 40 vias
v3: diameter 1.27, hole 0.711, Top Layer to Bottom Layer, 40 vias
v4: diameter 0.864, hole 0.406, Top Layer to Bottom Layer, tented bottom, 1 vias

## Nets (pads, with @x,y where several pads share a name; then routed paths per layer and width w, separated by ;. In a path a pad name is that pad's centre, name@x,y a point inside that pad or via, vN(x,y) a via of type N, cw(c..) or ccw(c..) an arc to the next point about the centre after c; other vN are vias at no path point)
AGND: C8A.1 C8B.1 C8C.1 C9A.2 C9B.2 C9C.2 C12.2 C13.1 C20.2 NT2.1 R31.1 R55.1 R56.1 R57.1 R58.1 U1.10 | length 71.9
  Top Layer w0.254: v2(117.1,22.6) 118.5,22.6 119.875,23.975 U1.10@119.875,25.375 119.875,28.325 118.5,29.7 C20.2@118.5,30.3
  Top Layer w0.5: R31.1@118.465,32.035 118.465,30.335 C20.2@118.5,30.3
  Top Layer w0.75: 109.5,27 109.5,32.8 110.3,33.6 117.882,33.6 118.748,32.735 R31.1@118.748,31.973
  Top Layer w1: NT2.1@78.484,18.97 80.43,18.97 83.1,16.3 v3(96.6,16.3)
  Bottom Layer w0.254: R58.1@20.3,27.7 21.437,27.7 v1(21.737,27.4) ; C12.2@30.8,21.2 C13.1@30.8,23.8 ; C9C.2@45.518,40.625 v1(45.518,42.025) C8C.1@45.518,43.425 ; C9B.2@99.518,40.634 v1(99.518,42.034) C8B.1@99.518,43.434 ; C9A.2@151.418,40.634 v1(151.418,42.034) C8A.1@151.418,43.434
  Bottom Layer w0.75: v3@96.6,16.7 96.6,17.8 97.6,18.8 v2(106.7,18.8)
  other v1: 30.8,22.5 85.8,22.8 80.6,26.1
  other v2: 87.6,15 92.8,15 87.6,17.5 92.8,17.5 106.7,21.3 96,22 106.7,23.7
  other v3: 42,20.9 47,20.9 52,20.9 78,21.1 74.4,21.2 113,35.9 55,36 60,36 71,36 76,36 108,36 128,36 161,36 60,40 76,40 133,40 146,40 71,40.1 94,45.9 141,45.9 146,45.9 43,46 60,46 71,46 76,46 81,46 86,46 123,46 128,46 133,46 151,46 156,46
DGND: C4.2 C11.2 C19.2 C21.2 C22.2 C23.2 C24.2 C25.2 J5.2 J6.5 NT2.2 P1.9 RF1.1 RF1.19 RF2.2 RF2.20 U1.12 U6.8 U7.2 U8.2 U9.2 U10.2 U11.2 U12.2 U13.2 U14.2 U15.2 U16.2 U17.2 U18.2 | length 413.9
  Top Layer w0.25: v2@118.575,23.7 U1.12@118.575,25.375
  Top Layer w0.254: v2(107.1,7.7) v2@107.143,7.744 ; U1.12@118.575,25.375 118.575,27.075 C11.2@118.6,27.1 ; v1@134.8,27.3 v1(134.8,27.4) ; U11.2@141.7,16.14 143.36,16.14 144.1,15.4 v2(146.2,15.4) 146.205,15.405 RF2.20@146.205,15.415 ; v3(154.2,3.6) 158.8,3.6 159.8,4.6 159.8,17.1 ; 159.8,18.5 159.8,17.1 ; v2(161,17) 159.9,17 159.8,17.1 ; v1(167.9,12.5) U10.2@169.16,12.5
  Top Layer w0.5: C4.2@113.9,25.4 113.9,24.9 115.1,23.7 v2@118.575,23.7 ; C19.2@114.775,30.4 114.775,28.825 115.321,28.279 117.481,28.279 118.435,27.325 C11.2@118.435,27.1 ; v2(144,12.2) 143.3,12.2 143,11.9 143,4.4 143.415,3.985 RF2.2@146.205,3.985 ; v2(146.2,15.4) 146.2,17.3 146.2,17.6 147.1,18.5 159.8,18.5 179.7,18.5 180.115,18.085 RF1.19@180.115,15.415 183.285,15.415 184,14.7 184,7.8 ; RF1.1@180.115,3.985 183.285,3.985 184,4.7 184,5.3 ; U8.2@183.5,5.3 184,5.3 ; U7.2@183.5,7.8 184,7.8 ; U15.2@183.5,9 184,9 ; 184,5.3 184,7.8
  Top Layer w0.75: v2@107.143,7.744 U6.8@107.143,9.129 107.143,10.743 107.5,11.1 C22.2@108.3,11.1 ; v1(110,20) C21.2@111.8,20
  Top Layer w1: C23.2@28.275,29.7 28.275,28.3 29.175,27.4 v1(30.3,27.4) 34.9,22.8 74.964,22.8 76.07,21.694 J5.2@76.07,18.97 77.787,18.97 ; 79.5,31.836 79.5,29.7 v1(81.8,27.4) ; v1@134.787,27.412 C24.2@137.775,30.4
  Bottom Layer w0.254: v2(107.1,7.7) 107.1,7.5 v2@107.2,7.4
  Bottom Layer w0.5: P1.9@86.14,3.53 88.97,0.7 93.5,0.7 ; 93.5,13.7 93.5,0.7 ; J6.5@106.93,2.7 106.93,0.7 ; v2@107.1,7.7 v2@107.143,7.744 ; v1(110,20) 114.446,20 114.8,20.354 114.8,23.2 115.2,23.6 118.3,23.6 v2(118.4,23.7) ; 111,1 U18.2@111,1.3 ; U17.2@112.2,1.3 112.2,0.7 106.93,0.7 ; v2(144,12.2) 146.2,14.4 v2(146.2,15.4) ; 93.5,0.7 106.93,0.7
  Bottom Layer w0.75: v2@107.13,7.7 107.13,4.6 96.5,4.6 95,6.1 95,18.2 96.8,20 v1(110,20)
  Bottom Layer w1: v1@30.575,27.4 v1(81.8,27.4) v1(134.8,27.4) ; J5.2@76.07,18.97 78.23,18.97 83.4,13.8 94.8,13.8
  other v1: 184,2 184,17
  other v2: 138.5,7.8 161.8,8.1
  other v3: 114.4,2.3 120,2.3 125.6,2.3 131.3,2.3
  other v4: 154.2,8.8
NetC4_1: C4.1 U1.14 | length 1.8
  Top Layer w0.254: C4.1@115.5,25.4 117.25,25.4 U1.14@117.275,25.375
NetC8A_2: C8A.2 C10A.2 R8A.2 U1.3 | length 47.1
  Top Layer w0.254: U1.3@124.425,25.375 124.4,25.4 124.4,26.003 124.457,26.061 124.457,27.011 126.4,28.953 126.4,38.7 v1(130.9,43.2)
  Bottom Layer w0.254: v1(130.9,43.2) 131.909,42.191 149.175,42.191 C10A.2@149.818,42.834 149.818,43.634 150.584,44.4 152.9,44.4 153.018,44.282 C8A.2@153.018,43.434 R8A.2@154.818,43.434
NetC8B_2: C8B.2 C10B.2 R8B.2 U1.7 | length 41.3
  Top Layer w0.254: v1(104.6,44.6) 104.6,42.885 105.385,42.1 113,42.1 121.825,33.275 U1.7@121.825,25.375
  Bottom Layer w0.254: C10B.2@97.818,42.834 97.818,44.034 98.118,44.334 101.1,44.334 ; C8B.2@101.118,43.434 101.118,44.316 101.1,44.334 ; 102.7,44.334 102.7,43.152 R8B.2@102.818,43.034 ; v1(104.6,44.6) 103.6,44.6 103.334,44.334 101.1,44.334
NetC8C_2: C8C.2 C10C.2 R8C.2 U1.5 | length 102.8
  Top Layer w0.254: v1(54.918,45.225) 57.168,45.225 58.302,44.091 96.791,44.091 99,46.3 99.357,46.657 114.789,46.657 124,37.447 124,27.847 123.125,26.972 U1.5@123.125,25.375
  Bottom Layer w0.254: C10C.2@43.018,42.825 43.018,44.025 43.418,44.425 46.118,44.425 C8C.2@47.118,43.425 ; R8C.2@48.618,43.425 C8C.2@47.118,43.425 ; v1(54.918,45.225) 48.918,45.225 C8C.2@47.118,43.425
NetC9A_1: C9A.1 C10A.1 R9A.2 U1.4 | length 48.7
  Top Layer w0.254: U1.4@123.775,25.375 123.775,26.975 125.3,28.5 125.9,29.1 125.9,39.2 v1@129.5,42.8
  Bottom Layer w0.254: v1(129.5,43) 130.766,41.734 149.266,41.734 149.7,41.3 C10A.1@149.7,41 ; C10A.1@149.818,41.234 149.818,39.682 150,39.5 152.678,39.5 152.86,39.682 152.86,40.634 C9A.1@153.018,40.634 R9A.2@154.818,40.634
NetC9B_1: C9B.1 C10B.1 R9B.2 U1.8 | length 40.1
  Top Layer w0.254: v1(104.4,39.4) 104.4,40.8 105.243,41.643 112.757,41.643 121.175,33.225 U1.8@121.175,25.375
  Bottom Layer w0.254: C10B.1@97.818,41.234 97.818,40.134 98.352,39.6 100.871,39.6 101.118,39.847 C9B.1@101.118,40.634 R9B.2@102.418,40.634 ; 101.1,39.829 103.071,39.829 103.5,39.4 v1(104.4,39.4)
NetC9C_1: C9C.1 C10C.1 R9C.2 U1.6 | length 105.6
  Top Layer w0.254: v1(54.918,38.825) 57.125,38.825 57.125,42.425 58.334,43.634 96.98,43.634 99.547,46.2 114.6,46.2 123.543,37.257 123.543,28.036 122.475,26.968 U1.6@122.475,25.375
  Bottom Layer w0.254: C10C.1@43.018,41.225 43.018,40.315 43.733,39.6 46.093,39.6 C9C.1@47.118,40.625 ; R9C.2@48.618,40.625 C9C.1@47.118,40.625 ; v1(54.918,38.825) 48.918,38.825 C9C.1@47.118,40.625
NetC12_1: C12.1 C14.1 R10.2 U1.1 | length 107.1
  Top Layer w0.254: v1(111.8,21.4) 112,21.2 118.643,21.2 120.323,22.88 121.915,22.88 122.435,23.4 125.387,23.4 125.725,23.738 U1.1@125.725,25.375
  Bottom Layer w0.254: R10.2@27.1,21.6 27.1,20.76 27.46,20.4 29.2,20.4 ; C12.1@29.2,21.2 29.2,20.4 ; v1@111.6,21.6 110.9,22.3 102,22.3 99.757,24.543 36.143,24.543 34.2,22.6 33.6,22.6 C14.1@32.5,21.5 32.5,20.658 31.437,19.595 30.163,19.595 29.358,20.4 29.2,20.4
NetC13_2: C13.2 C14.2 R11.2 U1.2 | length 106.2
  Top Layer w0.254: v1@112.5,22.5 113.3,21.7 118.497,21.7 120.134,23.337 121.726,23.337 122.246,23.857 125.075,23.857 U1.2@125.075,25.375
  Bottom Layer w0.254: R11.2@27.1,23.4 27.1,24.113 27.587,24.6 29.3,24.6 29.9,25.2 ; C13.2@29.2,23.8 29.2,24.6 ; 29.9,25.205 31.437,25.205 32.5,24.142 C14.2@32.5,23.1 34,23.1 36,25.1 100,25.1 102.3,22.8 112.3,22.8 v1(112.6,22.5)
NetC20_1: C20.1 U1.9 | length 5.3
  Top Layer w0.254: C20.1@119.7,30.3 119.7,29.6 120.525,28.775 U1.9@120.525,25.375
NetC21_1: C21.1 J6.4 P1.1 R16.2 U1.15 U18.1 | length 62.7
  Top Layer w0.254: P1.1@75.98,3.53 76.639,3.53 79.769,0.4 104.5,0.4 105.66,1.56 J6.4@105.66,2.7 105.66,3.56 106.07,3.97 110,3.97 v2(110,3.2) ; v2(110.9,11.8) 110.9,14.8 113,16.9 R16.2@113,18.2 113,19.9 C21.1@113.4,19.9 113.475,19.825 U1.15@117.275,19.825
  Bottom Layer w0.254: P1.1@75.95,3.3 P1.1@75.98,3.33 ; v2(110.9,11.8) 110.9,8.5 110.4,8 110.4,4.278 110.338,4.216 110.338,4.191 110,3.853 v2(110,3.2) 110.6,2.6 111,2.6 U18.1@111,2.14
NetC22_1: C22.1 C23.1 C24.1 C25.1 C28.1 D7.1 J10.3 J11.3 J12.3 RELA.9 RELB.9 RELC.9 U4.4 U5.1 U6.9 | length 277.9
  Top Layer w0.254: 34.325,34.55 34.345,34.53 ; RELB.9@90.508,37.292 RELB.9@90.508,37.3
  Top Layer w0.5: 107.143,12.757 U6.9@107.143,13.929
  Top Layer w0.75: C23.1@34.325,29.7 34.325,34.55 RELC.9@34.325,37.225 ; 34.345,34.53 42.19,34.53 J12.3@43.71,36.05 ; RELC.9@34.4,37.3 34.4,46.4 35.3,47.3 40.5,47.3 42.1,48.9 82.8,48.9 84.4,47.3 v3(90.508,47.3) 96.3,47.3 97.9,48.9 134.2,48.9 138.4,44.7 138.4,41.286 RELA.9@142.486,37.2 142.486,34.701 ; C25.1@79.5,39.3 88.5,39.3 90.508,37.292 v2(90.508,22) ; v2(90.5,15.1) v1(90.5,12.3) 93.2,12.3 93.4,12.1 106.5,12.1 107.143,12.743 ; RELB.9@90.508,37.3 92.508,39.3 96.16,39.3 J11.3@99.41,36.05 ; 107.143,12.757 107.6,12.3 C22.1@108.3,12.3 ; 142.486,29.639 142.486,34.701 ; J10.3@151.7,36.3 151.7,35.74 150.661,34.701 142.486,34.701
  Top Layer w1: RELC.9@34.325,37.225 RELC.9@34.4,37.3
  Bottom Layer w0.254: C28.1@56.8,12.375 C28.1@57.515,13.09 ; D7.1@61.7,13.09 D7.1@61.71,13.08
  Bottom Layer w0.5: 67.2,12.2 U4.4@67.2,13.08 U5.1@67.2,15.65 ; v1(90.5,12.3) v1@90.6,12.3 ; 90.5,20.4 90.508,20.408
  Bottom Layer w0.75: 67.2,12.2 68.5,10.9 87.1,10.9 88.5,12.3 v1(90.5,12.3) ; v2(90.5,15.1) 90.5,20.4 ; 90.508,20.408 v2(90.508,22) ; RELB.9@90.508,37.3 v3(90.508,47.3)
  Bottom Layer w1: C28.1@57.515,13.09 D7.1@61.7,13.09 ; D7.1@61.71,13.08 U4.4@67.2,13.08
NetC28_2: C28.2 D7.2 J5.1 R39.2 U4.3 U5.2 | length 26
  Bottom Layer w0.254: D7.2@61.7,17.51 D7.2@62.61,16.6 ; 61.7,19.1 61.8,19.2
  Bottom Layer w0.5: D7.2@62.61,16.6 U5.2@67.2,16.6
  Bottom Layer w1: C28.2@56.8,18.425 57.575,19.2 61.8,19.2 R39.2@65.1,19.2 65.7,19.2 U4.3@67.2,20.7 69.6,20.7 71.33,18.97 J5.1@73.53,18.97 ; D7.2@61.7,17.51 61.7,19.1
NetD1A_1: D1A.1 L2A.1 R6A.3 R6A.5 | length 15.2
  Bottom Layer w0.254: L2A.1@160.464,43.434 163.118,43.434 D1A.1@163.318,43.634 ; D1A.1@163.318,44.1 166.1,44.1 ; R6A.5@166.824,48.25 166.1,47.526 166.1,44.1 ; R6A.3@169.924,45.45 169.924,44.324 169.7,44.1 166.1,44.1
NetD1A_2: D1A.2 L1A.1 R6A.4 R6A.6 | length 19.1
  Bottom Layer w0.254: L1A.1@160.464,40.634 163.168,40.634 163.902,39.9 165.424,39.9 165.424,43.5 166.1,43.5 ; R6A.6@166.824,39.35 166.1,40.074 166.1,43.5 ; R6A.4@169.924,42.15 169.924,43.376 169.8,43.5 166.1,43.5
NetD1B_1: D1B.1 L2B.1 R6B.3 R6B.5 | length 15.4
  Bottom Layer w0.254: L2B.1@108.264,43.434 110.468,43.434 D1B.1@111.118,44.084 ; D1B.1@111.118,44.1 113.9,44.1 ; R6B.5@114.6,48.25 114.6,47.567 113.9,46.867 113.9,44.1 ; R6B.3@117.7,45.45 117.7,44.3 117.5,44.1 113.9,44.1
NetD1B_2: D1B.2 L1B.1 R6B.4 R6B.6 | length 17.7
  Bottom Layer w0.254: L1B.1@108.264,40.634 110.468,40.634 111.118,39.984 111.618,40.484 111.618,41.434 113.2,43.016 113.2,43.5 113.9,43.5 ; R6B.6@114.6,39.35 113.9,40.05 113.9,43.5 ; R6B.4@117.7,42.15 117.7,43.33 117.53,43.5 113.9,43.5
NetD1C_1: D1C.1 L2C.1 R6C.3 R6C.5 | length 17.5
  Bottom Layer w0.254: L2C.1@54.464,43.425 56.868,43.425 D1C.1@57.518,44.075 ; D1C.1@57.6,42.975 58.875,42.975 60,44.1 65.73,44.1 65.9,44.27 R6C.3@65.9,45.45 ; 62.17,44.1 62.17,47.37 R6C.5@62.8,48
